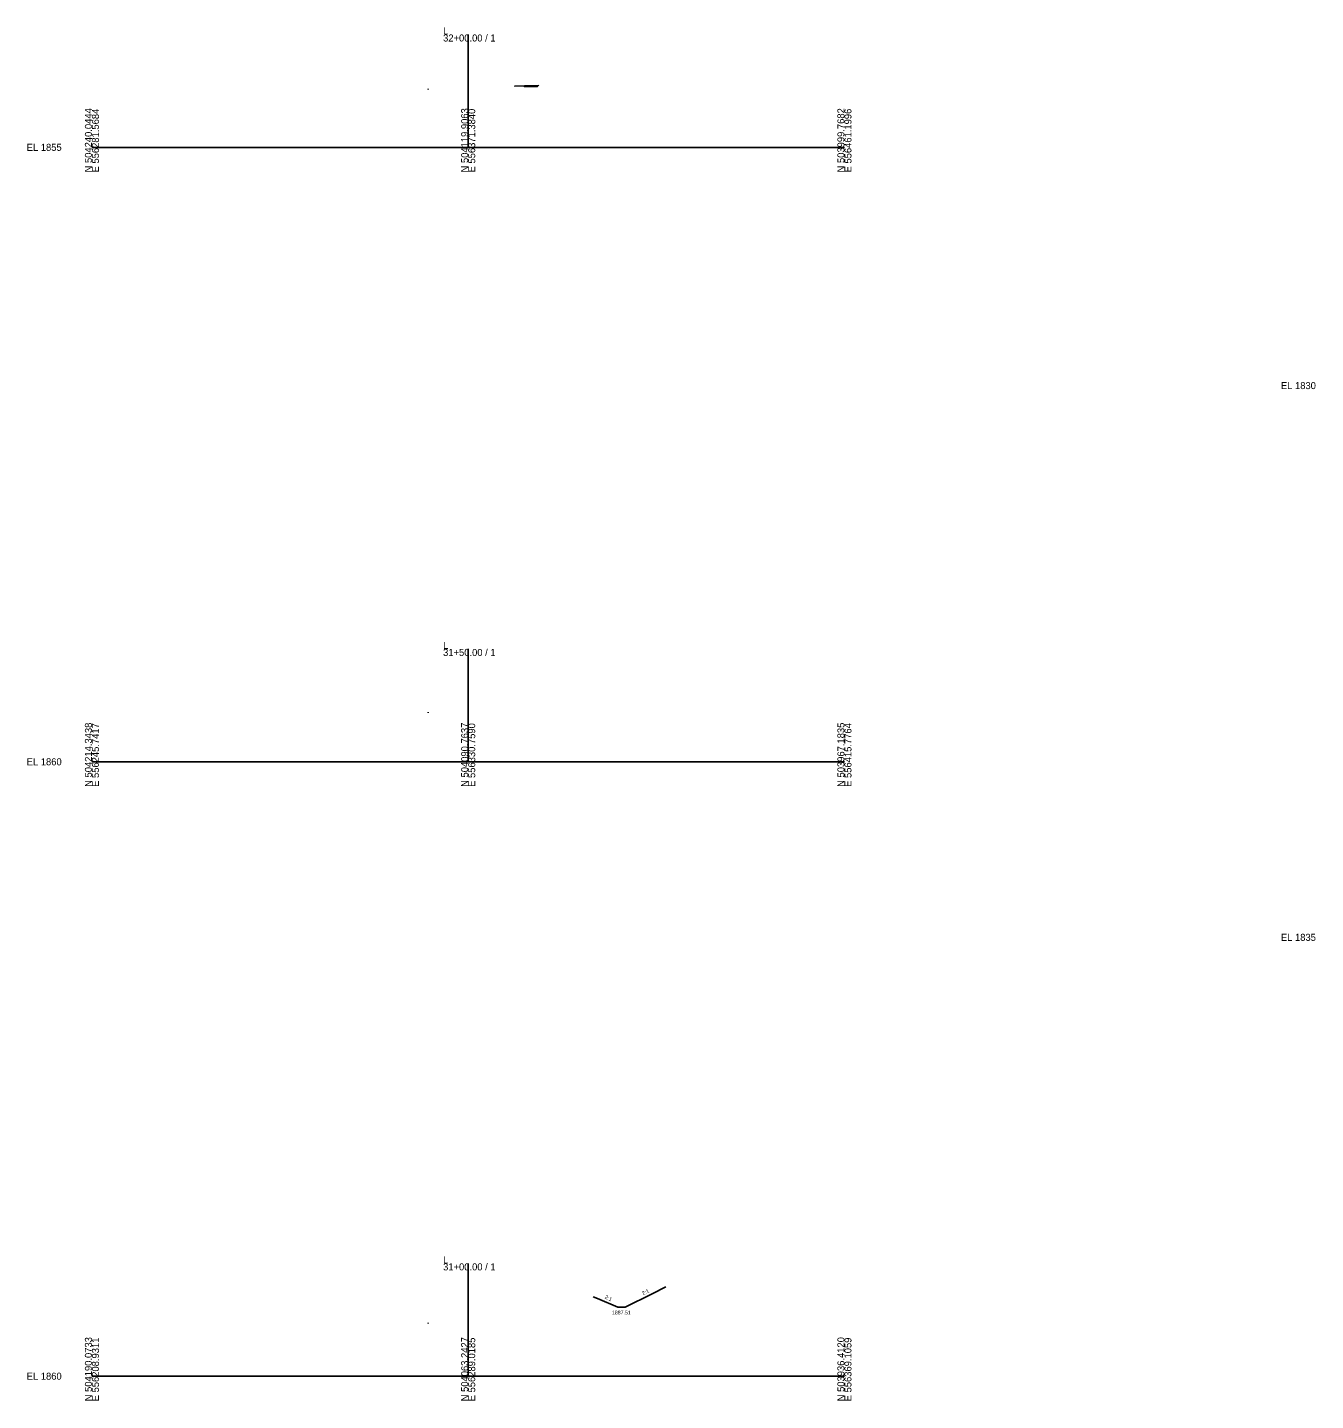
# Model space of a CAD drawing. Extents: x -26 to 3303, y -10 to 4703.
# Drawn here: x 974 to 1488, y 505 to 1053 of the extents above; entities that cross this region are included whole.
import ezdxf

# ---------------------------------------------------------------- set-up
doc = ezdxf.new("R2010")
doc.units = 0
for name, color, linetype in [('Exist Cross Section Cell', 7, 'Continuous'), ('Prop CMT Shear Line', 7, 'Continuous'), ('Prop XS Ditch Slope Text', 7, 'Continuous'), ('Prop XS Finish Grade', 7, 'Continuous'), ('Prop XS Label Text', 7, 'Continuous'), ('Scratch_Level_0', 7, 'Continuous'), ('Scratch_Level_9', 7, 'Continuous')]:
    doc.layers.add(name, color=color, linetype=linetype)

msp = doc.modelspace()

# ---------------------------------------------------------------- linework, layer by layer
at = {"layer": 'Exist Cross Section Cell'}
for p, q in [((1150, 1005), (1150, 1050)), ((1000, 1005), (1150, 1005)), ((1150, 1005), (1300, 1005)), ((1150, 760), (1150, 805)), ((1000, 760), (1150, 760)), ((1150, 760), (1300, 760)), ((1150, 515), (1150, 560)), ((1000, 515), (1150, 515)), ((1150, 515), (1300, 515))]:
    msp.add_line(p, q, dxfattribs=at)
at = {"layer": 'Prop XS Finish Grade'}
for points in [[(1228.8, 550.6), (1223.3, 547.85), (1212.63, 542.51)], [(1209.63, 542.51), (1209.63, 542.51), (1201.53, 545.96), (1199.89, 546.65)], [(1212.63, 542.51), (1209.63, 542.51), (1209.63, 542.51), (1209.63, 542.51), (1209.63, 542.51), (1209.63, 542.51), (1209.63, 542.51)]]:
    msp.add_lwpolyline(points, dxfattribs=at)
at = {"layer": 'Scratch_Level_0'}
for points in [[(1172.5, 1029.49), (1168.5, 1029.41), (1168.5, 1029.41)], [(1172.5, 1029.49), (1172.5, 1029.49), (1172.49, 1029.15), (1172.49, 1029.15), (1172.49, 1029.15), (1177.51, 1029.25), (1177.51, 1029.25), (1177.5, 1029.59), (1172.5, 1029.49)], [(1178, 1029.6), (1177.5, 1029.59), (1177.5, 1029.59)], [(1178.14, 1029.56), (1178, 1029.6), (1178, 1029.6)]]:
    msp.add_lwpolyline(points, dxfattribs=at)
at = {"layer": 'Scratch_Level_9'}
for points in [[(1134, 1028.35), (1134, 1028.1)], [(1134, 779.83), (1134, 779.58)], [(1134, 536.25), (1134, 536)]]:
    msp.add_lwpolyline(points, dxfattribs=at)

# ---------------------------------------------------------------- texts
at = {"layer": 'Exist Cross Section Cell'}
for s, p in [('L', (1140, 1050)), ('32+00.00 / 1', (1140, 1047.2)), ('EL 1855', (974, 1003.6)), ('EL 1830', (1474, 908.6)), ('31+50.00 / 1', (1140, 802.2)), ('L', (1140, 805)), ('EL 1860', (974, 758.6)), ('EL 1835', (1474, 688.6)), ('31+00.00 / 1', (1140, 557.2)), ('L', (1140, 560)), ('EL 1860', (974, 513.6))]:
    msp.add_text(s, height=2.8, dxfattribs=at).set_placement(p)
for s, p in [('N 504240.0444', (1000, 995)), ('E 556281.5684', (1002.8, 995)), ('N 504119.9063', (1150, 995)), ('E 556371.3840', (1152.8, 995)), ('N 503999.7682', (1300, 995)), ('E 556461.1996', (1302.8, 995)), ('N 504214.3438', (1000, 750)), ('E 556245.7417', (1002.8, 750)), ('N 504090.7637', (1150, 750)), ('E 556330.7590', (1152.8, 750)), ('N 503967.1835', (1300, 750)), ('E 556415.7764', (1302.8, 750)), ('N 504190.0733', (1000, 505)), ('E 556208.9311', (1002.8, 505)), ('N 504063.2427', (1150, 505)), ('E 556289.0185', (1152.8, 505)), ('N 503936.4120', (1300, 505)), ('E 556369.1059', (1302.8, 505))]:
    msp.add_text(s, height=2.8, rotation=90, dxfattribs=at).set_placement(p)
at = {"layer": 'Prop CMT Shear Line'}
msp.add_text('X', height=0.0025, dxfattribs=at).set_placement((1209.63, 542.51))
at = {"layer": 'Prop XS Ditch Slope Text'}
msp.add_text('1887.51', height=1.5, dxfattribs=at).set_placement((1207.31, 539.65))
at = {"layer": 'Prop XS Label Text'}
for rotation, p in [(26.5651, (1219.74, 547.26)), (333.4349, (1204.33, 546.11))]:
    msp.add_text('2:1', height=1.5, rotation=rotation, dxfattribs=at).set_placement(p)
at = {"layer": 'Scratch_Level_0'}
msp.add_text('X', height=0.0025, dxfattribs=at).set_placement((1172.5, 1029.48))

doc.saveas('drawing.dxf')
